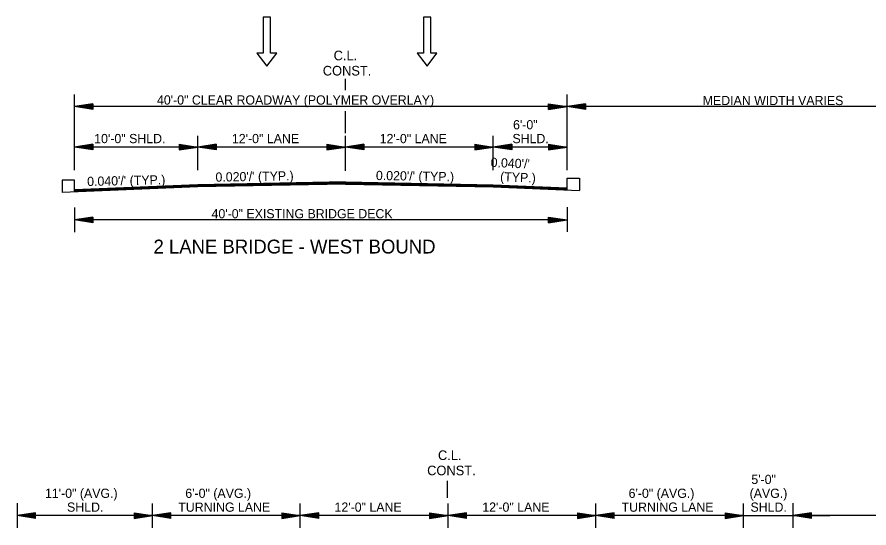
# Model space of a CAD drawing. Extents: x 550980 to 1930787, y -1972975 to 596640.
# Drawn here: x 551082 to 551774, y -1963653 to -1963238 of the extents above; entities that cross this region are included whole.
import ezdxf

# ---------------------------------------------------------------- set-up
doc = ezdxf.new("R2010")
doc.units = 0
doc.layers.add('R_Border', color=7, linetype='Continuous')
doc.layers.add('R_Draft', color=7, linetype='Continuous')

msp = doc.modelspace()

# ---------------------------------------------------------------- linework, layer by layer
at = {"layer": 'R_Border'}
for p, q in [((551128.87, -1963371.03), (551118.7, -1963371.03)), ((551118.7, -1963371.03), (551118.7, -1963380.84)), ((551128.87, -1963380.43), (551128.87, -1963371.03)), ((551528.87, -1963378.66), (551528.87, -1963369.26)), ((551528.87, -1963369.26), (551539.04, -1963369.26)), ((551539.04, -1963369.26), (551539.04, -1963379.24))]:
    msp.add_line(p, q, dxfattribs=at)
for points in [[(551277.03, -1963267.88), (551285.03, -1963278.27), (551293.03, -1963267.88), (551288.03, -1963267.88), (551288.03, -1963238.46), (551282.03, -1963238.46), (551282.03, -1963267.88)], [(551407.15, -1963267.88), (551415.15, -1963278.27), (551423.15, -1963267.88), (551418.15, -1963267.88), (551418.15, -1963238.46), (551412.15, -1963238.46), (551412.15, -1963267.88)]]:
    msp.add_lwpolyline(points, close=True, dxfattribs=at)
at = {"layer": 'R_Draft'}
for p, q in [((551348.87, -1963297.8), (551348.87, -1963288.5)), ((551128.87, -1963362.82), (551128.87, -1963301.33)), ((551528.87, -1963362.82), (551528.87, -1963301.33)), ((551143.87, -1963308.97), (551128.87, -1963311.22)), ((551528.87, -1963311.22), (551128.87, -1963311.22)), ((551143.87, -1963313.47), (551128.87, -1963311.22)), ((551143.87, -1963309.35), (551131.37, -1963311.22)), ((551143.87, -1963313.1), (551131.37, -1963311.22)), ((551143.87, -1963309.73), (551133.95, -1963311.22)), ((551143.87, -1963312.71), (551133.95, -1963311.22)), ((551143.87, -1963310.1), (551136.45, -1963311.22)), ((551143.87, -1963312.34), (551136.45, -1963311.22)), ((551143.87, -1963310.49), (551138.99, -1963311.22)), ((551143.87, -1963311.96), (551138.99, -1963311.22)), ((551143.87, -1963310.87), (551141.5, -1963311.22)), ((551143.87, -1963311.57), (551141.5, -1963311.22)), ((551143.87, -1963308.97), (551143.87, -1963313.47)), ((551488.87, -1963311.22), (551208.87, -1963311.22)), ((551513.87, -1963308.97), (551528.87, -1963311.22)), ((551513.87, -1963313.47), (551513.87, -1963308.97)), ((551513.87, -1963309.35), (551526.36, -1963311.22)), ((551513.87, -1963309.73), (551523.78, -1963311.22)), ((551513.87, -1963310.1), (551521.29, -1963311.22)), ((551513.87, -1963310.49), (551518.74, -1963311.22)), ((551513.87, -1963310.87), (551516.24, -1963311.22)), ((551513.87, -1963313.47), (551528.87, -1963311.22)), ((551513.87, -1963311.95), (551518.74, -1963311.22)), ((551513.87, -1963312.71), (551523.78, -1963311.22)), ((551513.87, -1963313.1), (551526.36, -1963311.22)), ((551513.87, -1963312.34), (551521.29, -1963311.22)), ((551513.87, -1963311.57), (551516.24, -1963311.22)), ((551543.87, -1963308.97), (551528.87, -1963311.22)), ((551543.87, -1963313.47), (551528.87, -1963311.22)), ((551868.87, -1963311.22), (551528.87, -1963311.22)), ((551543.87, -1963309.35), (551531.37, -1963311.22)), ((551543.87, -1963313.1), (551531.37, -1963311.22)), ((551543.87, -1963309.73), (551533.95, -1963311.22)), ((551543.87, -1963312.71), (551533.95, -1963311.22)), ((551543.87, -1963310.1), (551536.45, -1963311.22)), ((551543.87, -1963312.34), (551536.45, -1963311.22)), ((551543.87, -1963310.49), (551538.99, -1963311.22)), ((551543.87, -1963311.96), (551538.99, -1963311.22)), ((551543.87, -1963310.87), (551541.5, -1963311.22)), ((551543.87, -1963311.57), (551541.5, -1963311.22)), ((551543.87, -1963308.97), (551543.87, -1963313.47)), ((551348.87, -1963332.74), (551348.87, -1963314.98)), ((551228.87, -1963362.82), (551228.87, -1963334.86)), ((551348.87, -1963362.82), (551348.87, -1963334.86)), ((551348.87, -1963363.42), (551348.87, -1963334.86)), ((551468.87, -1963362.82), (551468.87, -1963334.86)), ((551143.87, -1963341.8), (551128.87, -1963344.05)), ((551228.87, -1963344.05), (551128.87, -1963344.05)), ((551143.87, -1963346.3), (551128.87, -1963344.05)), ((551143.87, -1963342.18), (551131.37, -1963344.05)), ((551143.87, -1963345.93), (551131.37, -1963344.05)), ((551143.87, -1963342.56), (551133.95, -1963344.05)), ((551143.87, -1963345.55), (551133.95, -1963344.05)), ((551143.87, -1963342.94), (551136.45, -1963344.05)), ((551143.87, -1963345.17), (551136.45, -1963344.05)), ((551143.87, -1963343.33), (551138.99, -1963344.05)), ((551143.87, -1963344.79), (551138.99, -1963344.05)), ((551143.87, -1963343.7), (551141.5, -1963344.05)), ((551143.87, -1963344.41), (551141.5, -1963344.05)), ((551143.87, -1963341.8), (551143.87, -1963346.3)), ((551213.87, -1963341.8), (551228.87, -1963344.05)), ((551213.87, -1963341.8), (551213.87, -1963346.3)), ((551213.87, -1963342.18), (551226.36, -1963344.05)), ((551213.87, -1963342.56), (551223.78, -1963344.05)), ((551213.87, -1963342.94), (551221.29, -1963344.05)), ((551213.87, -1963343.33), (551218.74, -1963344.05)), ((551213.87, -1963343.7), (551216.24, -1963344.05)), ((551213.87, -1963346.3), (551228.87, -1963344.05)), ((551213.87, -1963344.79), (551218.74, -1963344.05)), ((551213.87, -1963345.55), (551223.78, -1963344.05)), ((551213.87, -1963345.93), (551226.36, -1963344.05)), ((551213.87, -1963345.17), (551221.29, -1963344.05)), ((551213.87, -1963344.41), (551216.24, -1963344.05)), ((551243.87, -1963341.8), (551228.87, -1963344.05)), ((551348.87, -1963344.05), (551228.87, -1963344.05)), ((551243.87, -1963346.3), (551228.87, -1963344.05)), ((551243.87, -1963342.18), (551231.37, -1963344.05)), ((551243.87, -1963345.93), (551231.37, -1963344.05)), ((551243.87, -1963342.56), (551233.95, -1963344.05)), ((551243.87, -1963345.55), (551233.95, -1963344.05)), ((551243.87, -1963342.94), (551236.45, -1963344.05)), ((551243.87, -1963345.17), (551236.45, -1963344.05)), ((551243.87, -1963343.33), (551238.99, -1963344.05)), ((551243.87, -1963344.79), (551238.99, -1963344.05)), ((551243.87, -1963343.7), (551241.5, -1963344.05)), ((551243.87, -1963344.41), (551241.5, -1963344.05)), ((551243.87, -1963341.8), (551243.87, -1963346.3)), ((551333.87, -1963341.8), (551348.87, -1963344.05)), ((551333.87, -1963341.8), (551333.87, -1963346.3)), ((551333.87, -1963342.18), (551346.36, -1963344.05)), ((551333.87, -1963342.56), (551343.78, -1963344.05)), ((551333.87, -1963342.94), (551341.29, -1963344.05)), ((551333.87, -1963343.33), (551338.74, -1963344.05)), ((551333.87, -1963343.7), (551336.24, -1963344.05)), ((551333.87, -1963346.3), (551348.87, -1963344.05)), ((551333.87, -1963344.79), (551338.74, -1963344.05)), ((551333.87, -1963345.55), (551343.78, -1963344.05)), ((551333.87, -1963345.93), (551346.36, -1963344.05)), ((551333.87, -1963345.17), (551341.29, -1963344.05)), ((551333.87, -1963344.41), (551336.24, -1963344.05)), ((551363.87, -1963341.8), (551348.87, -1963344.05)), ((551468.87, -1963344.05), (551348.87, -1963344.05)), ((551363.87, -1963346.3), (551348.87, -1963344.05)), ((551363.87, -1963342.18), (551351.37, -1963344.05)), ((551363.87, -1963345.93), (551351.37, -1963344.05)), ((551363.87, -1963342.56), (551353.95, -1963344.05)), ((551363.87, -1963345.55), (551353.95, -1963344.05)), ((551363.87, -1963342.94), (551356.45, -1963344.05)), ((551363.87, -1963345.17), (551356.45, -1963344.05)), ((551363.87, -1963343.33), (551358.99, -1963344.05)), ((551363.87, -1963344.79), (551358.99, -1963344.05)), ((551363.87, -1963343.7), (551361.5, -1963344.05)), ((551363.87, -1963344.41), (551361.5, -1963344.05)), ((551363.87, -1963341.8), (551363.87, -1963346.3)), ((551453.87, -1963341.8), (551468.87, -1963344.05)), ((551453.87, -1963341.8), (551453.87, -1963346.3)), ((551453.87, -1963342.18), (551466.36, -1963344.05)), ((551453.87, -1963342.56), (551463.78, -1963344.05)), ((551453.87, -1963342.94), (551461.29, -1963344.05)), ((551453.87, -1963343.33), (551458.74, -1963344.05)), ((551453.87, -1963343.7), (551456.24, -1963344.05)), ((551453.87, -1963346.3), (551468.87, -1963344.05)), ((551453.87, -1963344.79), (551458.74, -1963344.05)), ((551453.87, -1963345.55), (551463.78, -1963344.05)), ((551453.87, -1963345.93), (551466.36, -1963344.05)), ((551453.87, -1963345.17), (551461.29, -1963344.05)), ((551453.87, -1963344.41), (551456.24, -1963344.05)), ((551483.87, -1963341.8), (551468.87, -1963344.05)), ((551528.87, -1963344.05), (551468.87, -1963344.05)), ((551483.87, -1963346.3), (551468.87, -1963344.05)), ((551483.87, -1963342.18), (551471.37, -1963344.05)), ((551483.87, -1963345.93), (551471.37, -1963344.05)), ((551483.87, -1963342.56), (551473.95, -1963344.05)), ((551483.87, -1963345.55), (551473.95, -1963344.05)), ((551483.87, -1963342.94), (551476.45, -1963344.05)), ((551483.87, -1963345.17), (551476.45, -1963344.05)), ((551483.87, -1963343.33), (551478.99, -1963344.05)), ((551483.87, -1963344.79), (551478.99, -1963344.05)), ((551483.87, -1963343.7), (551481.5, -1963344.05)), ((551483.87, -1963344.41), (551481.5, -1963344.05)), ((551483.87, -1963341.8), (551483.87, -1963346.3)), ((551513.87, -1963341.8), (551528.87, -1963344.05)), ((551513.87, -1963341.8), (551513.87, -1963346.3)), ((551513.87, -1963342.18), (551526.36, -1963344.05)), ((551513.87, -1963342.56), (551523.78, -1963344.05)), ((551513.87, -1963342.94), (551521.29, -1963344.05)), ((551513.87, -1963343.33), (551518.74, -1963344.05)), ((551513.87, -1963343.7), (551516.24, -1963344.05)), ((551513.87, -1963346.3), (551528.87, -1963344.05)), ((551513.87, -1963344.79), (551518.74, -1963344.05)), ((551513.87, -1963345.55), (551523.78, -1963344.05)), ((551513.87, -1963345.93), (551526.36, -1963344.05)), ((551513.87, -1963345.17), (551521.29, -1963344.05)), ((551513.87, -1963344.41), (551516.24, -1963344.05)), ((551348.87, -1963372.36), (551228.87, -1963374.76)), ((551348.87, -1963372.66), (551228.87, -1963375.06)), ((551348.87, -1963372.96), (551228.87, -1963375.36)), ((551348.87, -1963373.26), (551228.87, -1963375.66)), ((551348.87, -1963373.56), (551228.87, -1963375.96)), ((551348.87, -1963373.86), (551228.87, -1963376.26)), ((551348.87, -1963374.03), (551228.87, -1963376.43)), ((551348.87, -1963372.36), (551468.87, -1963374.76)), ((551348.87, -1963372.66), (551468.87, -1963375.06)), ((551348.87, -1963372.96), (551468.87, -1963375.36)), ((551348.87, -1963373.26), (551468.87, -1963375.66)), ((551348.87, -1963373.56), (551468.87, -1963375.96)), ((551348.87, -1963373.86), (551468.87, -1963376.26)), ((551348.87, -1963374.03), (551468.87, -1963376.43)), ((551228.87, -1963376.43), (551118.7, -1963380.84)), ((551228.87, -1963374.76), (551128.87, -1963378.76)), ((551228.87, -1963375.06), (551128.87, -1963379.06)), ((551228.87, -1963375.36), (551128.87, -1963379.36)), ((551228.87, -1963375.66), (551128.87, -1963379.66)), ((551228.87, -1963375.96), (551128.87, -1963379.96)), ((551228.87, -1963376.26), (551128.87, -1963380.26)), ((551468.87, -1963374.76), (551528.87, -1963377.16)), ((551468.87, -1963375.06), (551528.87, -1963377.46)), ((551468.87, -1963375.36), (551528.87, -1963377.76)), ((551468.87, -1963375.66), (551528.87, -1963378.06)), ((551468.87, -1963375.96), (551528.87, -1963378.36)), ((551468.87, -1963376.26), (551528.87, -1963378.66)), ((551468.87, -1963376.43), (551539.04, -1963379.24)), ((551128.87, -1963393.22), (551128.87, -1963413.22)), ((551528.87, -1963392.97), (551528.87, -1963412.97)), ((551143.87, -1963400.97), (551128.87, -1963403.22)), ((551143.87, -1963401.35), (551131.37, -1963403.22)), ((551143.87, -1963401.73), (551133.95, -1963403.22)), ((551143.87, -1963402.1), (551136.45, -1963403.22)), ((551143.87, -1963400.97), (551143.87, -1963405.47)), ((551513.87, -1963400.97), (551528.87, -1963403.22)), ((551513.87, -1963405.47), (551513.87, -1963400.97)), ((551513.87, -1963401.35), (551526.36, -1963403.22)), ((551513.87, -1963401.73), (551523.78, -1963403.22)), ((551513.87, -1963402.1), (551521.29, -1963403.22)), ((551143.87, -1963405.47), (551128.87, -1963403.22)), ((551518.87, -1963403.22), (551128.87, -1963403.22)), ((551143.87, -1963405.1), (551131.37, -1963403.22)), ((551143.87, -1963404.71), (551133.95, -1963403.22)), ((551143.87, -1963404.34), (551136.45, -1963403.22)), ((551143.87, -1963402.49), (551138.99, -1963403.22)), ((551143.87, -1963403.96), (551138.99, -1963403.22)), ((551143.87, -1963402.87), (551141.5, -1963403.22)), ((551143.87, -1963403.57), (551141.5, -1963403.22)), ((551513.87, -1963402.49), (551518.74, -1963403.22)), ((551513.87, -1963402.87), (551516.24, -1963403.22)), ((551513.87, -1963405.47), (551528.87, -1963403.22)), ((551513.87, -1963403.95), (551518.74, -1963403.22)), ((551513.87, -1963404.71), (551523.78, -1963403.22)), ((551513.87, -1963405.1), (551526.36, -1963403.22)), ((551513.87, -1963404.34), (551521.29, -1963403.22)), ((551513.87, -1963403.57), (551516.24, -1963403.22)), ((551431.76, -1963628.73), (551431.76, -1963615.06)), ((551082.19, -1963633.31), (551082.19, -1963653.31)), ((551192.19, -1963653.31), (551192.19, -1963633.42)), ((551312.2, -1963653.31), (551312.2, -1963633.42)), ((551432.2, -1963653.31), (551432.2, -1963633.42)), ((551552.2, -1963653.31), (551552.2, -1963633.42)), ((551672.2, -1963653.31), (551672.2, -1963633.42)), ((551712.2, -1963633.31), (551712.2, -1963653.31)), ((551097.19, -1963641.06), (551082.19, -1963643.31)), ((551192.19, -1963643.31), (551082.19, -1963643.31)), ((551097.19, -1963645.56), (551082.19, -1963643.31)), ((551097.19, -1963641.44), (551084.69, -1963643.31)), ((551097.19, -1963645.19), (551084.69, -1963643.31)), ((551097.19, -1963641.82), (551087.27, -1963643.31)), ((551097.19, -1963644.8), (551087.27, -1963643.31)), ((551097.19, -1963642.19), (551089.77, -1963643.31)), ((551097.19, -1963644.43), (551089.77, -1963643.31)), ((551097.19, -1963642.58), (551092.31, -1963643.31)), ((551097.19, -1963644.04), (551092.31, -1963643.31)), ((551097.19, -1963642.96), (551094.82, -1963643.31)), ((551097.19, -1963643.66), (551094.82, -1963643.31)), ((551097.19, -1963645.56), (551097.19, -1963641.06)), ((551177.19, -1963641.06), (551192.19, -1963643.31)), ((551177.19, -1963641.06), (551177.19, -1963645.56)), ((551177.19, -1963641.44), (551189.68, -1963643.31)), ((551177.19, -1963641.82), (551187.1, -1963643.31)), ((551177.19, -1963642.19), (551184.61, -1963643.31)), ((551177.19, -1963642.58), (551182.06, -1963643.31)), ((551177.19, -1963642.96), (551179.56, -1963643.31)), ((551177.19, -1963645.56), (551192.19, -1963643.31)), ((551177.19, -1963644.05), (551182.06, -1963643.31)), ((551177.19, -1963644.8), (551187.1, -1963643.31)), ((551177.19, -1963645.19), (551189.68, -1963643.31)), ((551177.19, -1963644.43), (551184.61, -1963643.31)), ((551177.19, -1963643.66), (551179.56, -1963643.31)), ((551207.2, -1963641.06), (551192.2, -1963643.31)), ((551312.2, -1963643.31), (551192.2, -1963643.31)), ((551207.2, -1963645.56), (551192.2, -1963643.31)), ((551207.2, -1963641.44), (551194.7, -1963643.31)), ((551207.2, -1963645.19), (551194.7, -1963643.31)), ((551207.2, -1963641.82), (551197.28, -1963643.31)), ((551207.2, -1963644.8), (551197.28, -1963643.31)), ((551207.2, -1963642.19), (551199.78, -1963643.31)), ((551207.2, -1963644.43), (551199.78, -1963643.31)), ((551207.2, -1963642.58), (551202.32, -1963643.31)), ((551207.2, -1963644.04), (551202.32, -1963643.31)), ((551207.2, -1963642.96), (551204.83, -1963643.31)), ((551207.2, -1963643.66), (551204.83, -1963643.31)), ((551207.2, -1963645.56), (551207.2, -1963641.06)), ((551297.2, -1963641.06), (551312.2, -1963643.31)), ((551297.2, -1963641.06), (551297.2, -1963645.56)), ((551297.2, -1963641.44), (551309.69, -1963643.31)), ((551297.2, -1963641.82), (551307.11, -1963643.31)), ((551297.2, -1963642.19), (551304.62, -1963643.31)), ((551297.2, -1963642.58), (551302.07, -1963643.31)), ((551297.2, -1963642.96), (551299.57, -1963643.31)), ((551297.2, -1963645.56), (551312.2, -1963643.31)), ((551297.2, -1963644.05), (551302.07, -1963643.31)), ((551297.2, -1963644.8), (551307.11, -1963643.31)), ((551297.2, -1963645.19), (551309.69, -1963643.31)), ((551297.2, -1963644.43), (551304.62, -1963643.31)), ((551297.2, -1963643.66), (551299.57, -1963643.31)), ((551327.2, -1963641.06), (551312.2, -1963643.31)), ((551432.2, -1963643.31), (551312.2, -1963643.31)), ((551327.2, -1963645.56), (551312.2, -1963643.31)), ((551327.2, -1963641.44), (551314.7, -1963643.31)), ((551327.2, -1963645.19), (551314.7, -1963643.31)), ((551327.2, -1963641.82), (551317.28, -1963643.31)), ((551327.2, -1963644.8), (551317.28, -1963643.31)), ((551327.2, -1963642.19), (551319.78, -1963643.31)), ((551327.2, -1963644.43), (551319.78, -1963643.31)), ((551327.2, -1963642.58), (551322.32, -1963643.31)), ((551327.2, -1963644.04), (551322.32, -1963643.31)), ((551327.2, -1963642.96), (551324.83, -1963643.31)), ((551327.2, -1963643.66), (551324.83, -1963643.31)), ((551327.2, -1963645.56), (551327.2, -1963641.06)), ((551417.2, -1963641.06), (551432.2, -1963643.31)), ((551417.2, -1963641.06), (551417.2, -1963645.56)), ((551417.2, -1963641.44), (551429.69, -1963643.31)), ((551417.2, -1963641.82), (551427.11, -1963643.31)), ((551417.2, -1963642.19), (551424.62, -1963643.31)), ((551417.2, -1963642.58), (551422.07, -1963643.31)), ((551417.2, -1963642.96), (551419.57, -1963643.31)), ((551417.2, -1963645.56), (551432.2, -1963643.31)), ((551417.2, -1963644.05), (551422.07, -1963643.31)), ((551417.2, -1963644.8), (551427.11, -1963643.31)), ((551417.2, -1963645.19), (551429.69, -1963643.31)), ((551417.2, -1963644.43), (551424.62, -1963643.31)), ((551417.2, -1963643.66), (551419.57, -1963643.31)), ((551447.2, -1963641.06), (551432.2, -1963643.31)), ((551447.2, -1963645.56), (551432.2, -1963643.31)), ((551552.2, -1963643.31), (551432.2, -1963643.31)), ((551447.2, -1963641.44), (551434.7, -1963643.31)), ((551447.2, -1963645.19), (551434.7, -1963643.31)), ((551447.2, -1963641.82), (551437.28, -1963643.31)), ((551447.2, -1963644.8), (551437.28, -1963643.31)), ((551447.2, -1963642.19), (551439.78, -1963643.31)), ((551447.2, -1963644.43), (551439.78, -1963643.31)), ((551447.2, -1963642.58), (551442.32, -1963643.31)), ((551447.2, -1963644.04), (551442.32, -1963643.31)), ((551447.2, -1963642.96), (551444.83, -1963643.31)), ((551447.2, -1963643.66), (551444.83, -1963643.31)), ((551447.2, -1963645.56), (551447.2, -1963641.06)), ((551537.2, -1963641.06), (551552.2, -1963643.31)), ((551537.2, -1963641.06), (551537.2, -1963645.56)), ((551537.2, -1963641.44), (551549.69, -1963643.31)), ((551537.2, -1963641.82), (551547.11, -1963643.31)), ((551537.2, -1963642.19), (551544.62, -1963643.31)), ((551537.2, -1963642.58), (551542.07, -1963643.31)), ((551537.2, -1963642.96), (551539.57, -1963643.31)), ((551537.2, -1963645.56), (551552.2, -1963643.31)), ((551537.2, -1963644.05), (551542.07, -1963643.31)), ((551537.2, -1963644.8), (551547.11, -1963643.31)), ((551537.2, -1963645.19), (551549.69, -1963643.31)), ((551537.2, -1963644.43), (551544.62, -1963643.31)), ((551537.2, -1963643.66), (551539.57, -1963643.31)), ((551567.2, -1963641.06), (551552.2, -1963643.31)), ((551672.2, -1963643.31), (551552.2, -1963643.31)), ((551567.2, -1963645.56), (551552.2, -1963643.31)), ((551567.2, -1963641.44), (551554.7, -1963643.31)), ((551567.2, -1963645.19), (551554.7, -1963643.31)), ((551567.2, -1963641.82), (551557.28, -1963643.31)), ((551567.2, -1963644.8), (551557.28, -1963643.31)), ((551567.2, -1963642.19), (551559.78, -1963643.31)), ((551567.2, -1963644.43), (551559.78, -1963643.31)), ((551567.2, -1963642.58), (551562.32, -1963643.31)), ((551567.2, -1963644.04), (551562.32, -1963643.31)), ((551567.2, -1963642.96), (551564.83, -1963643.31)), ((551567.2, -1963643.66), (551564.83, -1963643.31)), ((551567.2, -1963645.56), (551567.2, -1963641.06)), ((551657.2, -1963641.06), (551672.2, -1963643.31)), ((551657.2, -1963641.06), (551657.2, -1963645.56)), ((551657.2, -1963641.44), (551669.69, -1963643.31)), ((551657.2, -1963641.82), (551667.11, -1963643.31)), ((551657.2, -1963642.19), (551664.62, -1963643.31)), ((551657.2, -1963642.58), (551662.07, -1963643.31)), ((551657.2, -1963642.96), (551659.57, -1963643.31)), ((551657.2, -1963645.56), (551672.2, -1963643.31)), ((551657.2, -1963644.05), (551662.07, -1963643.31)), ((551657.2, -1963644.8), (551667.11, -1963643.31)), ((551657.2, -1963645.19), (551669.69, -1963643.31)), ((551657.2, -1963644.43), (551664.62, -1963643.31)), ((551657.2, -1963643.66), (551659.57, -1963643.31)), ((551672.2, -1963643.31), (551712.2, -1963643.31)), ((552062.19, -1963643.31), (551712.19, -1963643.31)), ((551727.2, -1963641.06), (551712.2, -1963643.31)), ((551727.2, -1963645.56), (551712.2, -1963643.31)), ((551712.2, -1963643.31), (551742.2, -1963643.31)), ((551727.2, -1963641.44), (551714.7, -1963643.31)), ((551727.2, -1963645.19), (551714.7, -1963643.31)), ((551727.2, -1963641.82), (551717.28, -1963643.31)), ((551727.2, -1963644.8), (551717.28, -1963643.31)), ((551727.2, -1963642.19), (551719.78, -1963643.31)), ((551727.2, -1963644.43), (551719.78, -1963643.31)), ((551727.2, -1963642.58), (551722.32, -1963643.31)), ((551727.2, -1963644.04), (551722.32, -1963643.31)), ((551727.2, -1963642.96), (551724.83, -1963643.31)), ((551727.2, -1963643.66), (551724.83, -1963643.31)), ((551727.2, -1963645.56), (551727.2, -1963641.06))]:
    msp.add_line(p, q, dxfattribs=at)

# ---------------------------------------------------------------- texts
for s, height, p in [('C.L.', 7.8, (551339.27, -1963273.56)), ('CONST.', 7.8, (551330.48, -1963285.93)), ('40\'-0" CLEAR ROADWAY (POLYMER OVERLAY)', 7.5, (551195.84, -1963309.55)), ('MEDIAN WIDTH VARIES', 7.5, (551638.99, -1963309.95)), ('6\'-0"', 7.5, (551484.96, -1963329.63)), ('10\'-0" SHLD.', 7.5, (551144.85, -1963340.88)), ('12\'-0" LANE', 7.5, (551256.69, -1963340.88)), ('12\'-0" LANE', 7.5, (551376.69, -1963340.88)), ('SHLD.', 7.5, (551484.46, -1963340.88)), ('40\'-0" EXISTING BRIDGE DECK', 7.5, (551240.13, -1963401.9)), ('2 LANE BRIDGE - WEST BOUND', 11.25, (551192.99, -1963430.46)), ('C.L.', 7.8, (551424.01, -1963598.15)), ('CONST.', 7.8, (551415.23, -1963610.52)), ('5\'-0" ', 7.5, (551678.47, -1963617.64)), ('11\'-0" (AVG.)', 7.5, (551104.88, -1963628.89)), ('6\'-0" (AVG.) ', 7.5, (551218.83, -1963628.89)), ('6\'-0" (AVG.) ', 7.5, (551578.83, -1963628.89)), ('(AVG.)', 7.5, (551677.08, -1963628.89)), ('SHLD.', 7.5, (551122.78, -1963640.14)), ('TURNING LANE', 7.5, (551213.1, -1963640.14)), ('12\'-0" LANE', 7.5, (551340.01, -1963640.14)), ('12\'-0" LANE', 7.5, (551460.01, -1963640.14)), ('TURNING LANE', 7.5, (551573.1, -1963640.14)), ('SHLD.', 7.5, (551677.79, -1963640.14))]:
    msp.add_text(s, height=height, dxfattribs=at).set_placement(p)
for s, rotation, p in [("  0.040'/'", 357.55203, (551461.1, -1963359.9)), ("0.040'/' (TYP.)", 1.31838, (551139.22, -1963375.7)), ("0.020'/' (TYP.)", 0.97192, (551243.39, -1963372.16)), ("0.020'/' (TYP.)", 359.02808, (551373.57, -1963370.79)), (' (TYP.)', 357.55203, (551471.57, -1963371.61))]:
    msp.add_text(s, height=7.5, rotation=rotation, dxfattribs=at).set_placement(p)

doc.saveas('drawing.dxf')
